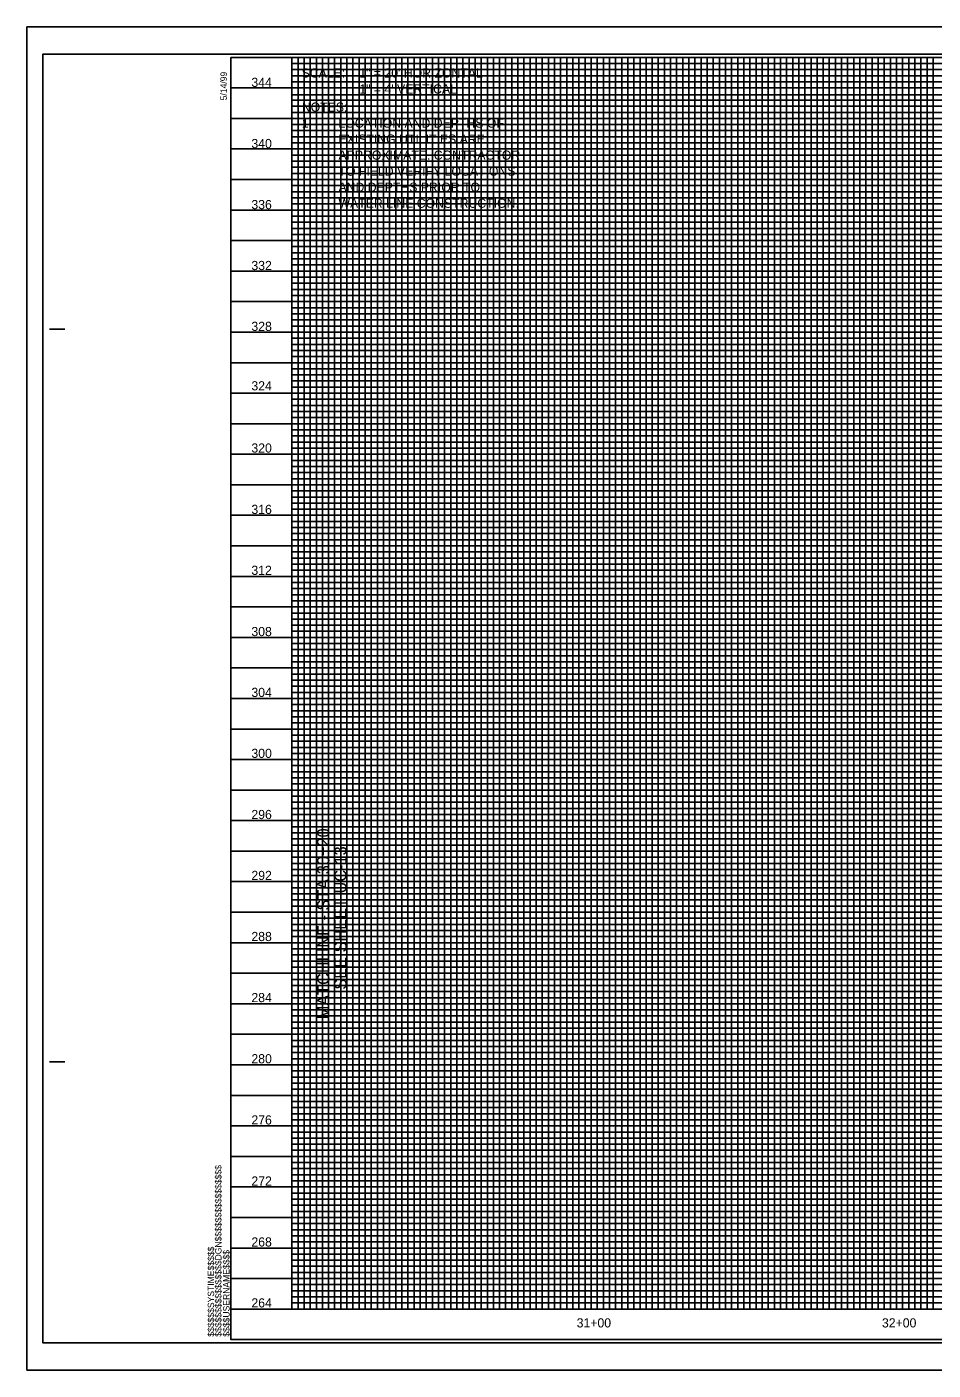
# Model space of a CAD drawing. Extents: x 3814791 to 3815465, y 1224203 to 1224643.
# Drawn here: x 3814791.3 to 3815088.1, y 1224203.2 to 1224643.2 of the extents above; entities that cross this region are included whole.
import ezdxf

# ---------------------------------------------------------------- set-up
doc = ezdxf.new("R2010")
doc.units = 0
for name, color, linetype in [('COGO Default Spiral', 7, 'Continuous'), ('Exist Roads EOP', 7, 'Continuous'), ('General Text and Text Box and Leader Line', 7, 'Continuous'), ('Pattern 49', 7, 'Continuous'), ('Scratch_Level_1', 7, 'Continuous'), ('W 45 B (St) CELL', 7, 'Continuous'), ('Water Line Text and Text Box and Leader Line (St)', 7, 'Continuous'), ('Water Pump Station (St) CELL', 7, 'Continuous')]:
    doc.layers.add(name, color=color, linetype=linetype)

msp = doc.modelspace()

# ---------------------------------------------------------------- linework, layer by layer
at = {"layer": 'COGO Default Spiral'}
msp.add_line((3814898.11, 1224443.21), (3814898.11, 1224263.21), dxfattribs=at)
at = {"layer": 'Exist Roads EOP'}
for p, q in [((3814878.11, 1224633.21), (3815378.11, 1224633.21)), ((3815438.11, 1224561.21), (3814878.11, 1224561.21)), ((3814878.11, 1224561.21), (3814878.11, 1224559.21)), ((3814878.11, 1224559.21), (3815438.11, 1224559.21)), ((3815438.11, 1224551.21), (3814878.11, 1224551.21)), ((3814798.71, 1224544.21), (3814803.71, 1224544.21)), ((3814798.71, 1224304.21), (3814803.71, 1224304.21)), ((3815458.11, 1224223.21), (3814858.11, 1224223.21)), ((3814878.11, 1224223.21), (3815438.11, 1224223.21)), ((3814858.11, 1224213.21), (3814858.11, 1224213.21)), ((3814858.11, 1224213.21), (3814858.11, 1224213.21)), ((3814858.11, 1224213.21), (3814858.11, 1224213.21)), ((3814858.11, 1224213.21), (3814858.11, 1224213.21)), ((3814858.11, 1224213.21), (3814858.11, 1224213.21)), ((3814858.11, 1224213.21), (3814858.11, 1224213.21))]:
    msp.add_line(p, q, dxfattribs=at)
for points in [[(3815458.11, 1224633.21), (3814858.11, 1224633.21), (3814858.11, 1224213.21), (3815458.11, 1224213.21)], [(3814878.11, 1224633.21), (3814878.11, 1224223.21), (3815438.11, 1224223.21), (3815438.11, 1224578.19), (3815378.11, 1224578.19), (3815378.11, 1224633.21)]]:
    msp.add_lwpolyline(points, close=True, dxfattribs=at)
for points in [[(3814878.11, 1224633.21), (3814878.11, 1224223.21), (3814898.11, 1224223.21), (3814898.11, 1224633.21), (3814918.11, 1224633.21), (3814918.11, 1224223.21), (3814938.11, 1224223.21), (3814938.11, 1224633.21), (3814958.11, 1224633.21), (3814958.11, 1224223.21), (3814978.11, 1224223.21), (3814978.11, 1224633.21), (3814998.11, 1224633.21), (3814998.11, 1224223.21), (3815018.11, 1224223.21), (3815018.11, 1224633.21), (3815038.11, 1224633.21), (3815038.11, 1224223.21), (3815058.11, 1224223.21), (3815058.11, 1224633.21), (3815078.11, 1224633.21), (3815078.11, 1224223.21), (3815098.11, 1224223.21)], [(3814878.11, 1224633.21), (3814880.11, 1224633.21), (3814880.11, 1224223.21), (3814882.11, 1224223.21), (3814882.11, 1224633.21), (3814884.11, 1224633.21), (3814884.11, 1224223.21), (3814886.11, 1224223.21), (3814886.11, 1224633.21), (3814890.11, 1224633.21), (3814890.11, 1224223.21), (3814892.11, 1224223.21), (3814892.11, 1224633.21), (3814894.11, 1224633.21), (3814894.11, 1224223.21), (3814896.11, 1224223.21), (3814896.11, 1224633.21), (3814900.11, 1224633.21), (3814900.11, 1224223.21), (3814902.11, 1224223.21), (3814902.11, 1224633.21), (3814904.11, 1224633.21), (3814904.11, 1224223.21), (3814906.11, 1224223.21), (3814906.11, 1224633.21), (3814910.11, 1224633.21), (3814910.11, 1224223.21), (3814912.11, 1224223.21), (3814912.11, 1224633.21), (3814914.11, 1224633.21), (3814914.11, 1224223.21), (3814916.11, 1224223.21), (3814916.11, 1224633.21), (3814920.11, 1224633.21), (3814920.11, 1224223.21), (3814922.11, 1224223.21), (3814922.11, 1224633.21), (3814924.11, 1224633.21), (3814924.11, 1224223.21), (3814926.11, 1224223.21), (3814926.11, 1224633.21), (3814930.11, 1224633.21), (3814930.11, 1224223.21), (3814932.11, 1224223.21), (3814932.11, 1224633.21), (3814934.11, 1224633.21), (3814934.11, 1224223.21), (3814936.11, 1224223.21), (3814936.11, 1224633.21), (3814940.11, 1224633.21), (3814940.11, 1224223.21), (3814942.11, 1224223.21), (3814942.11, 1224633.21), (3814944.11, 1224633.21), (3814944.11, 1224223.21)], [(3815378.09, 1224631.21), (3814878.11, 1224631.21), (3814878.11, 1224629.21), (3815378.09, 1224629.21)], [(3814888.11, 1224223.21), (3814888.11, 1224633.21), (3814908.11, 1224633.21), (3814908.11, 1224223.21), (3814928.11, 1224223.21), (3814928.11, 1224633.21), (3814948.11, 1224633.21), (3814948.11, 1224223.21), (3814968.11, 1224223.21), (3814968.11, 1224633.21), (3814988.11, 1224633.21), (3814988.11, 1224223.21), (3815008.11, 1224223.21), (3815008.11, 1224633.21), (3815028.11, 1224633.21), (3815028.11, 1224223.21), (3815048.11, 1224223.21), (3815048.11, 1224633.21), (3815068.11, 1224633.21), (3815068.11, 1224223.21), (3815088.11, 1224223.21), (3815088.11, 1224633.21)], [(3814944.11, 1224223.21), (3814946.11, 1224223.21), (3814946.11, 1224633.21), (3814950.11, 1224633.21), (3814950.11, 1224223.21), (3814952.11, 1224223.21), (3814952.11, 1224633.21), (3814954.11, 1224633.21), (3814954.11, 1224223.21), (3814956.11, 1224223.21), (3814956.11, 1224633.21), (3814960.11, 1224633.21), (3814960.11, 1224223.21), (3814962.11, 1224223.21), (3814962.11, 1224633.21), (3814962.11, 1224633.21), (3814964.11, 1224633.21), (3814964.11, 1224223.21), (3814966.11, 1224223.21), (3814966.11, 1224633.21), (3814970.11, 1224633.21), (3814970.11, 1224223.21), (3814972.11, 1224223.21), (3814972.11, 1224633.21), (3814974.11, 1224633.21), (3814974.11, 1224223.21), (3814976.11, 1224223.21), (3814976.11, 1224633.21), (3814980.11, 1224633.21), (3814980.11, 1224223.21), (3814982.11, 1224223.21), (3814982.11, 1224633.21), (3814984.11, 1224633.21), (3814984.11, 1224223.21), (3814986.11, 1224223.21), (3814986.11, 1224633.21), (3814990.11, 1224633.21), (3814990.11, 1224223.21), (3814992.11, 1224223.21), (3814992.11, 1224633.21), (3814994.11, 1224633.21), (3814994.11, 1224223.21), (3814996.11, 1224223.21), (3814996.11, 1224633.21), (3815000.11, 1224633.21), (3815000.11, 1224223.21), (3815002.11, 1224223.21), (3815002.11, 1224633.21), (3815004.11, 1224633.21), (3815004.11, 1224223.21), (3815006.11, 1224223.21), (3815006.11, 1224633.21), (3815010.11, 1224633.21), (3815010.11, 1224223.21), (3815016.11, 1224223.21), (3815016.11, 1224633.21), (3815020.11, 1224633.21), (3815020.11, 1224223.21), (3815022.11, 1224223.21), (3815022.11, 1224633.21), (3815024.11, 1224633.21), (3815024.11, 1224223.21), (3815026.11, 1224223.21), (3815026.11, 1224633.21), (3815030.11, 1224633.21), (3815030.11, 1224223.21), (3815032.11, 1224223.21), (3815032.11, 1224633.21), (3815034.11, 1224633.21), (3815034.11, 1224223.21), (3815036.11, 1224223.21), (3815036.11, 1224633.21), (3815040.11, 1224633.21), (3815040.11, 1224223.21), (3815042.11, 1224223.21), (3815042.11, 1224633.21), (3815044.11, 1224633.21), (3815044.11, 1224223.21), (3815046.11, 1224223.21), (3815046.11, 1224633.21), (3815050.11, 1224633.21), (3815050.11, 1224223.21), (3815052.11, 1224223.21), (3815052.11, 1224633.21), (3815054.11, 1224633.21), (3815054.11, 1224223.21), (3815056.11, 1224223.21), (3815056.11, 1224633.21), (3815060.11, 1224633.21), (3815060.11, 1224223.21), (3815062.11, 1224223.21), (3815062.11, 1224633.21), (3815064.11, 1224633.21), (3815064.11, 1224223.21), (3815066.11, 1224223.21), (3815066.11, 1224633.21), (3815070.11, 1224633.21), (3815070.11, 1224223.21)], [(3815012.11, 1224633.21), (3815012.11, 1224223.21), (3815014.11, 1224223.21), (3815014.11, 1224633.21)], [(3815012.11, 1224632.97), (3815012.11, 1224223.21), (3815014.11, 1224223.21), (3815014.11, 1224632.97)], [(3815072.11, 1224633.21), (3815072.11, 1224223.21), (3815074.11, 1224223.21), (3815074.11, 1224633.21), (3815076.11, 1224633.21), (3815076.11, 1224223.21), (3815080.11, 1224223.21), (3815080.11, 1224633.21), (3815082.11, 1224633.21), (3815082.11, 1224223.21), (3815084.11, 1224223.21), (3815084.11, 1224633.21), (3815086.11, 1224633.21), (3815086.11, 1224223.21)], [(3815378.09, 1224627.21), (3814878.11, 1224627.21), (3814878.11, 1224625.21), (3815378.09, 1224625.21)], [(3815378.09, 1224603.21), (3814858.15, 1224603.21), (3814858.15, 1224623.19), (3815378.09, 1224623.19)], [(3815378.09, 1224620.91), (3814878.11, 1224620.91), (3814878.11, 1224619.21), (3815378.09, 1224619.21)], [(3815378.09, 1224617.21), (3814878.11, 1224617.21), (3814878.11, 1224615.21), (3815378.09, 1224615.21)], [(3814858.11, 1224613.21), (3815378.09, 1224613.21)], [(3815378.09, 1224611.21), (3814878.11, 1224611.21), (3814878.11, 1224609.21), (3815378.09, 1224609.21)], [(3815378.11, 1224607.21), (3814878.11, 1224607.21), (3814878.11, 1224605.21), (3815378.09, 1224605.21)], [(3815378.09, 1224601.21), (3814878.11, 1224601.21), (3814878.11, 1224599.21), (3815378.09, 1224599.21)], [(3815378.09, 1224597.21), (3814878.11, 1224597.21), (3814878.11, 1224595.21), (3815378.09, 1224595.21)], [(3815378.09, 1224593.21), (3814858.11, 1224593.21), (3814858.11, 1224573.19), (3815458.11, 1224573.19)], [(3815378.09, 1224591.21), (3814878.11, 1224591.21), (3814878.11, 1224589.21), (3815378.09, 1224589.21)], [(3815378.09, 1224587.21), (3814878.11, 1224587.21), (3814878.11, 1224585.21), (3815378.09, 1224585.21)], [(3815458.11, 1224563.21), (3814858.11, 1224563.21), (3814858.11, 1224583.21), (3815378.09, 1224583.21)], [(3815378.09, 1224581.21), (3814878.11, 1224581.21), (3814878.11, 1224579.21), (3815378.09, 1224579.21)], [(3815438.11, 1224577.21), (3814878.11, 1224577.21), (3814878.11, 1224577.21), (3814878.11, 1224569.21), (3815438.11, 1224569.21)], [(3815438.11, 1224577.21), (3814878.11, 1224577.21), (3814878.11, 1224577.21), (3814878.11, 1224569.21), (3815458.11, 1224569.21)], [(3814878.11, 1224575.21), (3815438.11, 1224575.21)], [(3815438.11, 1224571.21), (3814878.11, 1224571.21)], [(3815438.11, 1224567.21), (3814878.11, 1224567.21), (3814878.11, 1224565.21), (3815438.11, 1224565.21)], [(3815438.11, 1224557.21), (3814878.11, 1224557.21), (3814878.11, 1224555.21), (3815438.11, 1224555.21)], [(3815458.11, 1224553.21), (3814858.11, 1224553.21), (3814858.11, 1224533.21), (3815458.11, 1224533.21)], [(3815438.11, 1224549.21), (3814878.11, 1224549.21), (3814878.11, 1224547.21), (3815438.11, 1224547.21)], [(3815458.11, 1224523.21), (3814858.11, 1224523.21), (3814858.11, 1224543.21), (3815458.11, 1224543.21)], [(3815438.11, 1224545.21), (3814878.11, 1224545.21)], [(3814878.11, 1224541.21), (3815438.11, 1224541.21)], [(3815438.11, 1224539.21), (3814878.11, 1224539.21), (3814878.11, 1224537.21), (3815438.11, 1224537.21)], [(3815438.11, 1224535.21), (3814878.11, 1224535.21), (3814878.11, 1224531.21), (3815438.11, 1224531.21)], [(3815438.11, 1224529.21), (3814878.11, 1224529.21), (3814878.11, 1224527.21), (3815438.11, 1224527.21)], [(3815438.11, 1224525.21), (3814878.11, 1224525.21), (3814878.11, 1224521.21), (3815438.11, 1224521.21)], [(3815438.11, 1224519.21), (3814878.11, 1224519.21), (3814878.11, 1224517.21), (3815438.11, 1224517.21)], [(3815458.11, 1224513.21), (3814858.11, 1224513.21), (3814858.11, 1224493.21), (3815458.11, 1224493.21)], [(3815438.11, 1224515.21), (3814878.11, 1224515.21), (3814878.11, 1224511.21), (3815438.11, 1224511.21)], [(3815438.11, 1224509.21), (3814878.11, 1224509.21), (3814878.11, 1224507.21), (3815438.11, 1224507.21)], [(3815458.11, 1224483.21), (3814858.11, 1224483.21), (3814858.11, 1224503.21), (3815458.11, 1224503.21)], [(3815438.11, 1224505.21), (3814878.11, 1224505.21), (3814878.11, 1224501.21), (3815438.11, 1224501.21)], [(3815438.11, 1224499.21), (3814878.11, 1224499.21), (3814878.11, 1224497.21), (3815438.11, 1224497.21)], [(3815438.11, 1224495.21), (3814878.11, 1224495.21), (3814878.11, 1224491.21), (3815438.11, 1224491.21)], [(3815438.11, 1224489.21), (3814878.11, 1224489.21), (3814878.11, 1224487.21), (3815438.11, 1224487.21)], [(3815438.11, 1224485.21), (3814878.11, 1224485.21), (3814878.11, 1224481.21), (3815438.11, 1224481.21)], [(3815438.11, 1224479.21), (3814878.11, 1224479.21), (3814878.11, 1224477.21), (3815438.11, 1224477.21)], [(3815458.11, 1224473.21), (3814858.11, 1224473.21), (3814858.11, 1224453.21), (3815458.11, 1224453.21)], [(3815438.11, 1224475.21), (3814878.11, 1224475.21), (3814878.11, 1224471.21), (3815438.11, 1224471.21)], [(3815438.11, 1224469.21), (3814878.11, 1224469.21), (3814878.11, 1224467.21), (3815438.11, 1224467.21)], [(3815458.11, 1224443.21), (3814858.11, 1224443.21), (3814858.11, 1224463.21), (3815458.11, 1224463.21)], [(3815438.11, 1224465.21), (3814878.11, 1224465.21), (3814878.11, 1224461.21), (3815438.11, 1224461.21)], [(3815438.11, 1224459.21), (3814878.11, 1224459.21), (3814878.11, 1224457.21), (3815438.11, 1224457.21)], [(3815438.11, 1224455.21), (3814878.11, 1224455.21), (3814878.11, 1224451.21), (3815438.11, 1224451.21)], [(3815438.11, 1224449.21), (3814878.11, 1224449.21), (3814878.11, 1224447.21), (3815438.11, 1224447.21)], [(3815438.11, 1224445.21), (3814878.11, 1224445.21), (3814878.11, 1224441.21), (3815438.11, 1224441.21)], [(3815438.11, 1224439.21), (3814878.11, 1224439.21), (3814878.11, 1224437.21), (3815438.11, 1224437.21)], [(3815458.11, 1224433.21), (3814858.11, 1224433.21), (3814858.11, 1224413.21), (3815458.11, 1224413.21)], [(3815438.11, 1224435.21), (3814878.11, 1224435.21), (3814878.11, 1224431.21), (3815438.11, 1224431.21)], [(3815438.11, 1224429.21), (3814878.11, 1224429.21), (3814878.11, 1224427.21), (3815438.11, 1224427.21)], [(3815458.11, 1224403.21), (3814858.11, 1224403.21), (3814858.11, 1224423.21), (3815458.11, 1224423.21)], [(3815438.11, 1224425.21), (3814878.11, 1224425.21)], [(3814878.11, 1224421.21), (3815438.11, 1224421.21)], [(3815438.11, 1224419.21), (3814878.11, 1224419.21), (3814878.11, 1224417.21), (3815438.11, 1224417.21)], [(3815438.11, 1224415.21), (3814878.11, 1224415.21), (3814878.11, 1224411.21), (3815438.11, 1224411.21)], [(3815438.11, 1224409.21), (3814878.11, 1224409.21), (3814878.11, 1224407.21), (3815438.11, 1224407.21)], [(3815438.11, 1224405.21), (3814878.11, 1224405.21), (3814878.11, 1224401.21), (3815438.11, 1224401.21)], [(3815438.11, 1224399.21), (3814878.11, 1224399.21), (3814878.11, 1224397.21), (3815438.11, 1224397.21)], [(3815458.11, 1224393.21), (3814858.11, 1224393.21), (3814858.11, 1224373.21), (3815458.11, 1224373.21)], [(3815438.11, 1224395.21), (3814878.11, 1224395.21), (3814878.11, 1224391.21), (3815438.11, 1224391.21)], [(3815438.11, 1224389.21), (3814878.11, 1224389.21), (3814878.11, 1224387.21), (3815438.11, 1224387.21)], [(3815438.11, 1224385.21), (3814878.11, 1224385.21), (3814878.11, 1224381.21), (3815438.11, 1224381.21)], [(3815458.11, 1224363.21), (3814858.11, 1224363.21), (3814858.11, 1224383.21), (3815458.11, 1224383.21)], [(3815438.11, 1224379.21), (3814878.11, 1224379.21), (3814878.11, 1224377.21), (3815438.11, 1224377.21)], [(3815438.11, 1224375.21), (3814878.11, 1224375.21), (3814878.11, 1224371.21), (3815438.11, 1224371.21)], [(3815438.11, 1224369.21), (3814878.11, 1224369.21), (3814878.11, 1224367.21), (3815438.11, 1224367.21)], [(3815438.11, 1224365.21), (3814878.11, 1224365.21), (3814878.11, 1224361.21), (3815438.11, 1224361.21)], [(3815438.11, 1224359.21), (3814878.11, 1224359.21), (3814878.11, 1224357.21), (3815438.11, 1224357.21)], [(3815458.11, 1224353.21), (3814858.11, 1224353.21), (3814858.11, 1224333.21), (3815458.11, 1224333.21)], [(3815438.11, 1224355.21), (3814878.11, 1224355.21), (3814878.11, 1224351.21), (3815438.11, 1224351.21)], [(3815438.11, 1224349.21), (3814878.11, 1224349.21), (3814878.11, 1224347.21), (3815438.11, 1224347.21)], [(3815438.11, 1224345.21), (3814878.11, 1224345.21), (3814878.11, 1224341.21), (3815438.11, 1224341.21)], [(3815458.11, 1224323.21), (3814858.11, 1224323.21), (3814858.11, 1224343.21), (3815458.11, 1224343.21)], [(3815438.11, 1224339.21), (3814878.11, 1224339.21), (3814878.11, 1224337.21), (3815438.11, 1224337.21)], [(3815438.11, 1224335.21), (3814878.11, 1224335.21), (3814878.11, 1224331.21), (3815438.11, 1224331.21)], [(3815438.11, 1224329.21), (3814878.11, 1224329.21), (3814878.11, 1224327.21), (3815438.11, 1224327.21)], [(3815438.11, 1224325.21), (3814878.11, 1224325.21), (3814878.11, 1224321.21), (3815438.11, 1224321.21)], [(3815438.11, 1224319.21), (3814878.11, 1224319.21), (3814878.11, 1224317.21), (3815438.11, 1224317.21)], [(3815458.11, 1224313.21), (3814858.11, 1224313.21), (3814858.11, 1224293.21), (3815458.11, 1224293.21)], [(3815438.11, 1224315.21), (3814878.11, 1224315.21), (3814878.11, 1224311.21), (3815438.11, 1224311.21)], [(3815438.11, 1224309.21), (3814878.11, 1224309.21), (3814878.11, 1224307.21), (3815438.11, 1224307.21)], [(3815438.11, 1224305.21), (3814878.11, 1224305.21)], [(3815458.11, 1224283.21), (3814858.11, 1224283.21), (3814858.11, 1224303.21), (3815458.11, 1224303.21)], [(3814878.11, 1224301.21), (3815438.11, 1224301.21)], [(3815438.11, 1224299.21), (3814878.11, 1224299.21), (3814878.11, 1224297.21), (3815438.11, 1224297.21)], [(3815438.11, 1224295.21), (3814878.11, 1224295.21)], [(3814878.11, 1224291.21), (3815438.11, 1224291.21)], [(3815438.11, 1224289.21), (3814878.11, 1224289.21), (3814878.11, 1224287.21), (3815438.11, 1224287.21)], [(3815438.11, 1224285.21), (3814878.11, 1224285.21), (3814878.11, 1224281.21), (3815438.11, 1224281.21)], [(3815438.11, 1224279.21), (3814878.11, 1224279.21), (3814878.11, 1224277.21), (3815438.11, 1224277.21)], [(3815438.11, 1224275.21), (3814878.11, 1224275.21), (3814878.11, 1224271.21), (3815438.11, 1224271.21)], [(3815458.11, 1224273.21), (3814858.11, 1224273.21), (3814858.11, 1224253.21), (3815458.11, 1224253.21)], [(3815438.11, 1224269.21), (3814878.11, 1224269.21), (3814878.11, 1224267.21), (3815438.11, 1224267.21)], [(3815438.11, 1224265.21), (3814878.11, 1224265.21), (3814878.11, 1224261.21), (3815438.11, 1224261.21)], [(3815458.11, 1224243.21), (3814858.11, 1224243.21), (3814858.11, 1224263.21), (3815458.11, 1224263.21)], [(3815438.11, 1224259.21), (3814878.11, 1224259.21), (3814878.11, 1224257.21), (3815438.11, 1224257.21)], [(3815438.11, 1224255.21), (3814878.11, 1224255.21), (3814878.11, 1224251.21), (3815438.11, 1224251.21)], [(3815438.11, 1224249.21), (3814878.11, 1224249.21), (3814878.11, 1224247.21), (3815438.11, 1224247.21)], [(3815438.11, 1224245.21), (3814878.11, 1224245.21), (3814878.11, 1224241.21), (3815438.11, 1224241.21)], [(3815438.11, 1224239.21), (3814878.11, 1224239.21), (3814878.11, 1224237.21), (3815438.11, 1224237.21)], [(3815438.11, 1224235.21), (3814878.11, 1224235.21), (3814878.11, 1224231.21), (3815438.11, 1224231.21)], [(3815458.11, 1224233.21), (3814858.11, 1224233.21)], [(3815438.11, 1224229.21), (3814878.11, 1224229.21), (3814878.11, 1224227.21), (3815438.11, 1224227.21)], [(3815438.11, 1224225.21), (3814878.11, 1224225.21)], [(3814873.11, 1224213.21), (3814873.11, 1224213.21)]]:
    msp.add_lwpolyline(points, dxfattribs=at)
at = {"layer": 'Pattern 49'}
msp.add_lwpolyline([(3815463.11, 1224634.23), (3814796.51, 1224634.23), (3814796.51, 1224212.19), (3815463.11, 1224212.19)], close=True, dxfattribs=at)
at = {"layer": 'Scratch_Level_1'}
msp.add_lwpolyline([(3815464.91, 1224643.21), (3814791.31, 1224643.21), (3814791.31, 1224203.21), (3815464.91, 1224203.21)], close=True, dxfattribs=at)

# ---------------------------------------------------------------- texts
at = {"layer": 'Exist Roads EOP'}
for s, p in [('5/14/99', (3814856.81, 1224619.13)), ('$$$$$$$$$$$$$$$$DGN$$$$$$$$$$$$$$$$', (3814855.05, 1224214.15)), ('$$$$$$SYSTIME$$$$$', (3814852.63, 1224214.15)), ('$$$$USERNAME$$$$', (3814857.68, 1224214.16))]:
    msp.add_text(s, height=2.1, rotation=90, dxfattribs=at).set_placement(p)
at = {"layer": 'General Text and Text Box and Leader Line'}
for s, p in [('344', (3814864.84, 1224623.54)), ('340', (3814864.84, 1224603.49)), ('336', (3814864.84, 1224583.5)), ('332', (3814864.84, 1224563.54)), ('328', (3814864.84, 1224543.61)), ('324', (3814864.84, 1224524.13)), ('320', (3814864.84, 1224503.75)), ('316', (3814864.84, 1224483.65)), ('312', (3814864.84, 1224463.71)), ('308', (3814864.84, 1224443.64)), ('304', (3814864.84, 1224423.71)), ('300', (3814864.84, 1224403.74)), ('296', (3814864.84, 1224383.71)), ('292', (3814864.84, 1224363.75)), ('288', (3814864.84, 1224343.75)), ('284', (3814864.84, 1224323.74)), ('280', (3814864.84, 1224303.71)), ('276', (3814864.84, 1224283.67)), ('272', (3814864.84, 1224263.65)), ('268', (3814864.84, 1224243.7)), ('264', (3814864.84, 1224223.74))]:
    msp.add_text(s, height=3, dxfattribs=at).set_placement(p)
at = {"layer": 'W 45 B (St) CELL'}
for s, p in [('SCALE: ', (3814881.28, 1224626.62)), ('1" = 20\' HORIZONTAL', (3814900.19, 1224626.62)), ('1" = 4\' VERTICAL', (3814900.19, 1224621.37)), ('NOTES:', (3814881.36, 1224615.43)), ('1.', (3814881.36, 1224610.18)), ('LOCATION AND DEPTHS OF', (3814893.36, 1224610.18)), ('EXISTING UTILITIES ARE', (3814893.36, 1224604.94)), ('APPROXIMATE. CONTRACTOR', (3814893.36, 1224599.69)), ('TO FIELD VERIFY LOCATIONS', (3814893.36, 1224594.44)), ('AND DEPTHS PRIOR TO', (3814893.36, 1224589.19)), ('WATER LINE CONSTRUCTION.', (3814893.36, 1224583.94))]:
    msp.add_text(s, height=3, dxfattribs=at).set_placement(p)
at = {"layer": 'Water Line Text and Text Box and Leader Line (St)'}
for s, p in [('MATCHLINE - STA.30+20', (3814890.39, 1224318.1)), ('SEE SHEET UC-13', (3814895.99, 1224327.83))]:
    msp.add_text(s, height=4, rotation=90, dxfattribs=at).set_placement(p)
at = {"layer": 'Water Pump Station (St) CELL'}
for s, p in [('31+00', (3814971.37, 1224217.19)), ('32+00', (3815071.35, 1224217.19))]:
    msp.add_text(s, height=3, dxfattribs=at).set_placement(p)

doc.saveas('drawing.dxf')
